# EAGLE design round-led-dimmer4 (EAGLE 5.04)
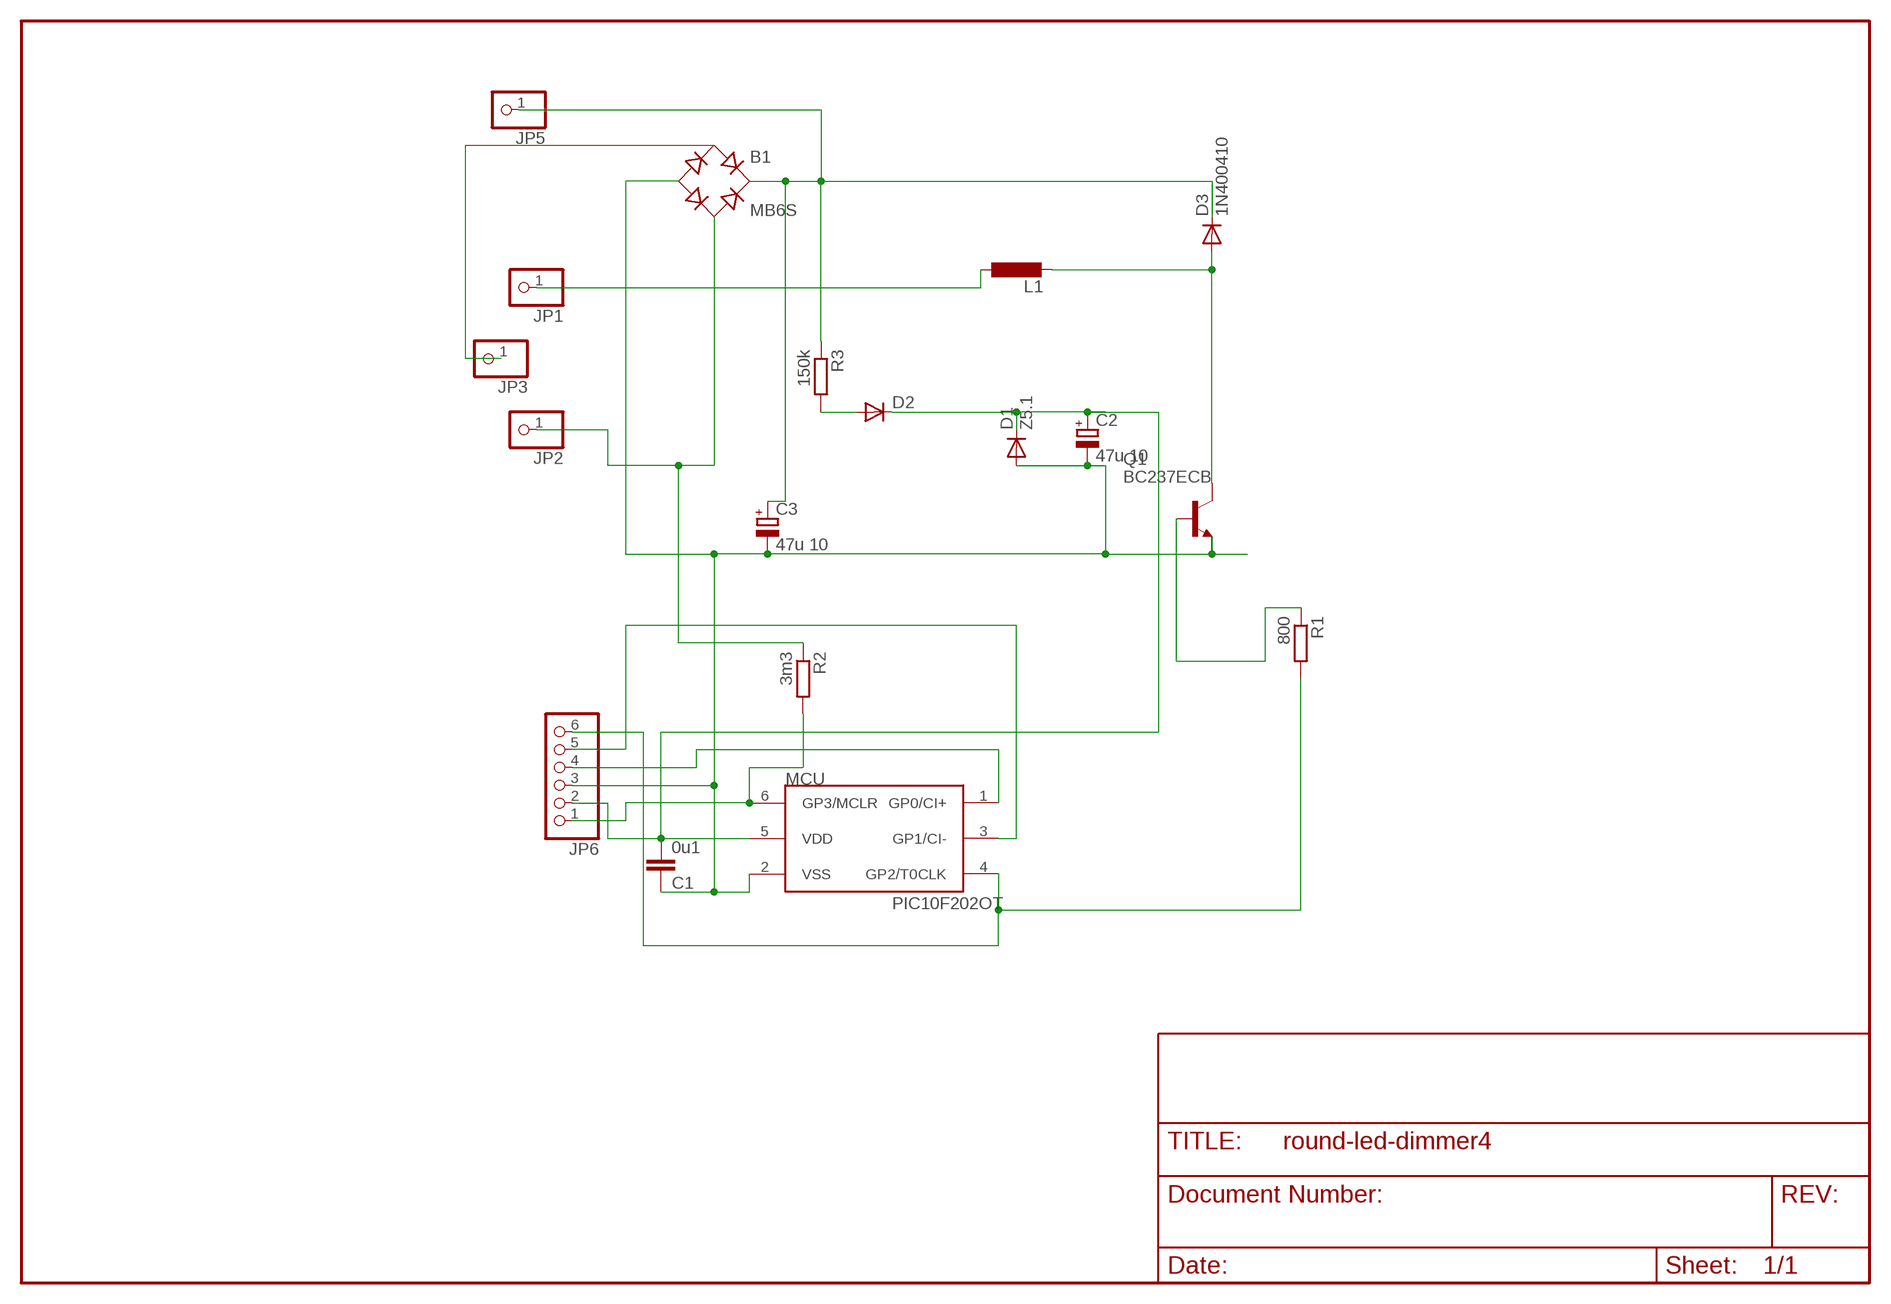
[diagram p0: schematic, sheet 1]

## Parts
B1  MB6S  [SOIC-4]
C1  0u1  C-EUC1206  [C1206]
C2  47u 10  CPOL-EUE2.5-5  [E2,5-5]
C3  47u 10  CPOL-EUE2.5-5  [E2,5-5]
D1  Z5.1  DIODE-MINIMELF  [MINIMELF]
D2  DIODE-D-2.5  [D-2.5]
D3  1N400410  [DO41-10]
JP1  PINHD-1X1  [1X01]
JP2  PINHD-1X1  [1X01]
JP3  PINHD-1X1  [1X01]
JP5  PINHD-1X1  [1X01]
JP6  PINHD-1X6  [1X06]
L1  L-EU0204/5  [0204/5]
MCU  PIC10F202OT  [SOT23-6]
Q1  BC237ECB  [TO92-BCE]
R1  800  R-EU_R1206  [R1206]
R2  3m3  R-EU_R1206  [R1206]
R3  150k  R-EU_R1206  [R1206]

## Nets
AC(N): B1.~2(AC2) JP2.1 R2.1
GATE: Q1.E(B) R1.1
GP0: JP6.4 MCU.1(GP0/CI+)
GP1: JP6.5 MCU.3(GP1/CI-)
GP2: JP6.6 MCU.4(GP2/T0CLK) R1.2
GP3: JP6.1 MCU.6(GP3/MCLR) R2.2
N$1: D3.A L1.2 Q1.C
N$2: JP1.1 L1.1
N$4: B1.+ C3.+ D3.C JP5.1 R3.1
N$5: D2.A R3.2
N$7: B1.~1(AC1) JP3.1
VDD: C1.2 C2.+ D1.C D2.C JP6.2 MCU.5(VDD)
VSS: B1.- C1.1 C2.- C3.- D1.A JP6.3 MCU.2(VSS) Q1.B(E)

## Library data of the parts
B1 = rectifier:MB*S: Bridge Rectifier Source: http://www.fairchildsemi.com/ds/MB/MB6S.pdf
C1 = rcl:C-EU: CAPACITOR, European symbol
C2 C3 = rcl:CPOL-EU: POLARIZED CAPACITOR, European symbol
D1 D2 = diode:DIODE-: DIODE
D3 = diode-1:1N4004: DIODE
JP1-JP3 JP5 = pinhead(2):PINHD-1X1: PIN HEADER
JP6 = pinhead(2):PINHD-1X6: PIN HEADER
L1 = rcl-2:L-EU: INDUCTOR, European symbol
MCU = microchip-3:PIC10F2*: uPC nW 0,25/0,5k Program Flash memory Comparator
Q1 = transistor-npn:BC237: NPN Transistor
R1-R3 = rcl:R-EU_: RESISTOR, European symbol

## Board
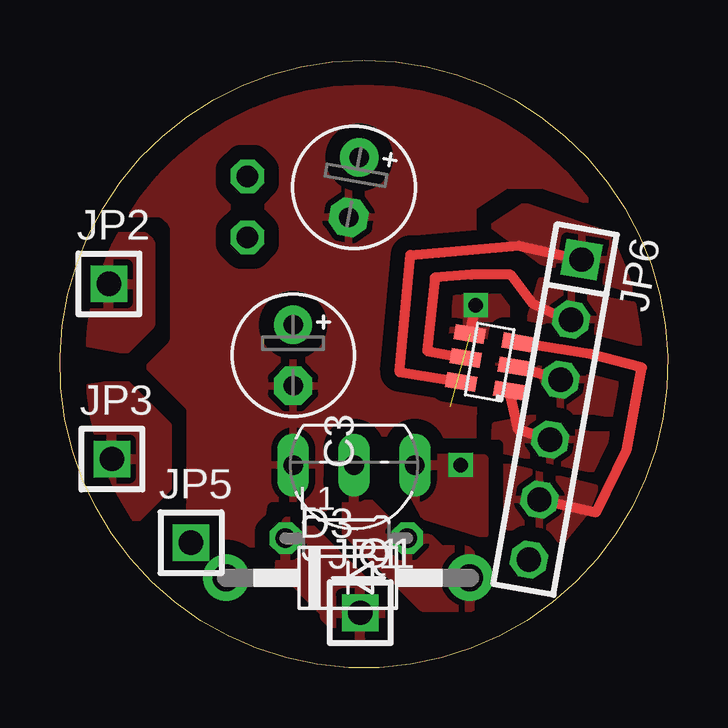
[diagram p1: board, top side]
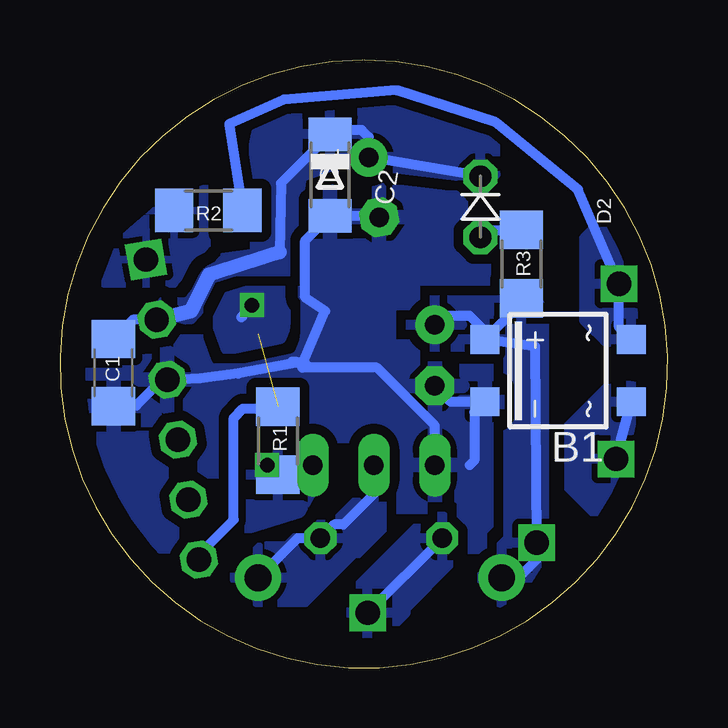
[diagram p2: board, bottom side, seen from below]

Size 25.35 x 25.34 mm. Coordinates in mm from the lower left corner, seen from the top.
Outline: 12.7,25.34 arc-360 12.64,25.34
Copper layers (1*16): Top 0.035mm / dielectric 1.5mm / Bottom 0.035mm
Design rules "default": minimum track width 10mil, minimum drill 24mil, track to track 8mil, track to pad 8mil, pad to pad 8mil, via to via 8mil, smd to smd 8mil, copper to edge 40mil, drill to drill 8mil, minimum pad ring 10mil, minimum via ring 8mil, stop-mask expansion 4mil, vias tented up to drill 0mil, thermal gap 10mil

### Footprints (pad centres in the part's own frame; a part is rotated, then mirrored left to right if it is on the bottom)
SOIC-4 = smd 1.2 x 1.2: + 1.3,3.05; - -1.3,3.05; ~1 -1.3,-3.05; ~2 1.3,-3.05
C1206 = smd 1.6 x 1.8: 1 -1.4,0; 2 1.4,0
E2,5-5 = drill 0.813 pad 1.6 round: + -1.27,0 | drill 0.813 pad 1.6 octagon: - 1.27,0
MINIMELF = smd 1.4 x 1.8: A 1.7,0; C -1.7,0
D-2.5 = drill 0.9 octagon: A 1.27,0; C -1.27,0
DO41-10 = drill 1.118 pad 1.93 round: A 5.08,0; C -5.08,0
1X01 = drill 1.016 square: 1 0,0
1X06 = drill 1.016 square: 1 -6.35,0 | drill 1.016 octagon: 2 -3.81,0; 3 -1.27,0; 4 1.27,0; 5 3.81,0; 6 6.35,0
0204/5 = drill 0.813 octagon: 1 -2.54,0; 2 2.54,0
SOT23-6 = smd 0.635 x 1.27: 1 -1.016,-1.016; 2 0,-1.016; 3 1.016,-1.016; 4 1.016,1.016; 5 0,1.016; 6 -1.016,1.016
TO92-BCE = drill 0.813 long: B 2.54,0; C 0,0; E -2.54,0
R1206 = smd 1.6 x 1.803: 1 -1.422,0; 2 1.422,0

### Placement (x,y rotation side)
B1  4.58,12.38 90 bottom
C1  23.11,12.3 90 bottom
C2  12.26,20.03 260 top
C3  9.72,13.02 270 top
D1  14.09,20.54 270 bottom
D2  7.81,19.21 270 bottom
D3  12.01,3.75 0 top
JP1  12.51,2.29 0 top
JP2  2.04,16 0 top
JP3  2.16,8.7 0 top
JP5  5.47,5.21 0 top
JP6  20.65,10.76 260 top
L1  11.94,5.4 0 top
MCU  17.91,12.74 80 top
Q1  12.26,8.45 180 top
R1  16.26,9.46 90 bottom
R2  19.16,19.06 180 bottom
R3  6.11,16.82 90 bottom

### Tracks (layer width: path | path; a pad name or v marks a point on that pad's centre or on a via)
AC(N)
  Bottom 0.406: B1.~2 2.04,14.19 JP2.1 3.75,19.94 7.18,22.73 11.31,24.07 16.01,23.69 18.29,22.67 R2.1
  pour Bottom (isolate 0.406, rank 3): 0.7,13.78 0.7,16.96 1.91,18.16 3.24,18.16 3.5,17.91 3.5,14.48 2.48,13.46
  pour Top (isolate 0.61, rank 2): 0.96,13.59 0.96,16.76 2.16,17.97 3.5,17.97 3.75,17.72 3.75,14.29 2.74,13.27
GATE  (via drill 0.6)
  Bottom 0.406: Q1.E R1.1
  other vias: 16.71,8.45
  pour Bottom (isolate 0.305): 14.61,7.75 14.55,8.89 17.72,8.83 17.72,5.72 15.31,6.48
  pour Top: 14.55,7.62 14.48,8.76 17.66,8.7 17.66,5.59 15.24,6.35
GP0
  Top 0.406: MCU.1 19.12,9.91 JP6.4
  pour Top (isolate 0.61, rank 2): 18.17,10.1 18.1,9.14 22.48,8.19 22.86,9.91 20.01,10.48
GP1
  Top 0.406: MCU.3 22.1,13.08 24.26,12.51 23.63,9.08 22.36,6.48 JP6.5
  pour Top (isolate 0.61, rank 2): 17.98,8.51 17.47,6.16 20.96,5.33 21.91,6.48 22.29,7.49 19.75,8.13
GP2  (via drill 0.6)  (1 unrouted)
  Top 0.406: MCU.4 v17.34,15.11
  Bottom 0.406: JP6.6 19.55,4.71 18.1,6.16 18.1,10.41 17.72,10.8 16.35,10.8 R1.2 | v17.34,15.11 17.78,14.61
  pour Bottom (isolate 0.61): 15.88,15.62 19.18,15.62 18.36,13.34 16.2,13.78 16.07,14.1 15.94,15.05 15.94,15.11 15.94,15.37
  pour Top (isolate 0.61): 16.07,15.94 19.37,15.94 18.55,13.65 16.39,14.1 16.26,14.42 16.13,15.37 16.13,15.43 16.13,15.69
GP3
  Top 0.406: MCU.6 14.16,12.32 14.61,17.21 19.12,17.59 JP6.1
  pour Bottom (isolate 0.61): 22.8,17.84 23.5,16 20.58,16 19.18,17.65 18.74,19.75 17.15,19.81 17.59,20.57 20.96,19.43
  pour Top (isolate 0.61, rank 2): 19.37,19.24 22.86,18.03 23.88,15.75 20.07,16.96 18.1,18.42
N$1
  Bottom 0.406: Q1.C 12.26,7.24 13.53,5.97 13.91,5.97 L1.2 15.44,5.4 D3.A
  pour Bottom (isolate 0.406, rank 2): 11.94,7.3 11.94,5.33 12.51,4.76 13.09,4.76 15.12,2.73 17.15,2.73 18.04,3.62 18.04,4 16.96,5.08 15.88,5.08 14.99,5.97 13.97,5.97 12.83,7.11
  pour Top (isolate 0.406, rank 2): 11.94,7.11 11.94,5.14 12.51,4.57 13.09,4.57 15.12,2.54 17.15,2.54 18.04,3.43 18.04,3.81 16.96,4.89 15.88,4.89 14.99,5.78 13.97,5.78 12.83,6.92
N$2
  Bottom 0.406: JP1.1 L1.1
  pour Top (isolate 0.61): 9.47,6.1 10.16,6.1 13.34,2.92 13.34,1.27 11.88,1.27 11.05,2.1 11.05,2.29 9.15,4.19
  pour Bottom (isolate 0.406): 9.34,6.29 10.04,6.29 13.21,3.11 13.21,1.46 11.75,1.46 10.93,2.29 10.93,2.48 9.02,4.38
N$4
  Bottom 0.406: B1.+ 5.53,13.4 JP5.1 5.47,4.51 6.23,3.75 D3.C | B1.+ 7.63,14.04 8.26,14.67 9.34,14.67 C3.+ | R3.1 6.11,15.2 B1.+
  pour Bottom (isolate 0.61, rank 2): 7.75,4.38 7.75,3.43 7.05,2.73 6.42,2.73 5.15,4.76 5.15,14.8 5.4,15.3 10.42,15.3 10.74,14.99 10.74,13.84 10.29,13.4 6.86,13.4 6.67,13.21 6.67,5.4 7.43,4.64
N$5
  Bottom 0.406: R3.2 7.51,18.25 D2.A
N$7
  Bottom 0.406: JP3.1 B1.~1
  pour Bottom (isolate 0.406, rank 3): 1.59,11.75 2.48,11.75 4.13,10.1 4.13,7.49 2.67,6.03 2.48,6.03 1.47,7.05 1.47,7.87 0.77,8.57 0.77,11.56 0.7,11.62
  pour Top (isolate 0.406, rank 2): 1.91,11.75 2.8,11.75 4.45,10.1 4.45,7.49 2.99,6.03 2.8,6.03 1.78,7.05 1.78,7.87 1.08,8.57 1.08,11.56 1.02,11.62
VDD
  Top 0.406: MCU.5 15.31,13.21 15.63,16.26 17.15,16.38 18.8,16.38 19.73,15.16 20.82,14.63 JP6.2
  Bottom 0.406: D2.C C2.+ 12.48,22.13 12.77,22.42 13.91,22.42 D1.C 16.13,20.19 16.2,17.34 | JP6.2 22.3,14.51 C1.2
  Bottom 0.61: 16.2,17.34 19.12,16.38 19.88,14.86 JP6.2
  pour Top (isolate 0.61, rank 2): 20.07,16.13 19.56,14.42 24.2,13.21 23.88,15.11 22.8,15.3 22.17,15.62
  pour Bottom (isolate 0.406, rank 3): 7.18,20.57 7.18,22.04 7.56,22.42 11.63,23.75 16.96,23.31 17.59,20.26 17.21,17.27 19.5,16.96 21.4,14.86 19.94,14.48 18.55,16 15.94,16 15.24,20.45 13.53,21.08 8.83,20.51
VSS
  Top 0.406: JP6.3 MCU.2
  Bottom 0.406: C1.1 23.09,10.92 22.17,10.92 21.08,12.01 JP6.3 20.32,12.01 19.5,12.07 17.91,12.26 15.18,12.76 14.29,14.86 15.12,15.43 15.12,17.81 D1.A 12.1,18.84 C2.- | 8.26,8.45 8.07,8.64 8.07,10.64 B1.- 9.05,11.08 C3.- | Q1.B 9.72,10.1 12.13,12.51 15.24,12.51 | 15.5,12.76 15.69,12.76 14.99,12.57
  pour Bottom (isolate 0.305): 19.37,13.02 19.37,11.37 21.72,10.8 22.8,11.3 22.55,12.83 21.15,13.02
  pour Top (isolate 0.61): 19.82,12.38 19.63,11.18 22.8,10.61 23.12,12.19
  pour Top (isolate 0.61, rank 3): 12.32,25.08 7.43,23.81 3.5,21.08 1.08,17.4 0.45,11.37 1.91,6.16 6.61,1.72 15.69,0.57 20.32,3.05 24.26,7.56 23.94,18.23 18.67,23.56
  pour Bottom (isolate 0.406, rank 4): 7.88,24.38 17.34,24.32 21.15,21.65 25.02,16.32 25.09,9.4 21.59,3.56 16.39,0.64 10.1,0.25 3.56,3.87 0.45,9.34 0.7,15.56 3.37,20.96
